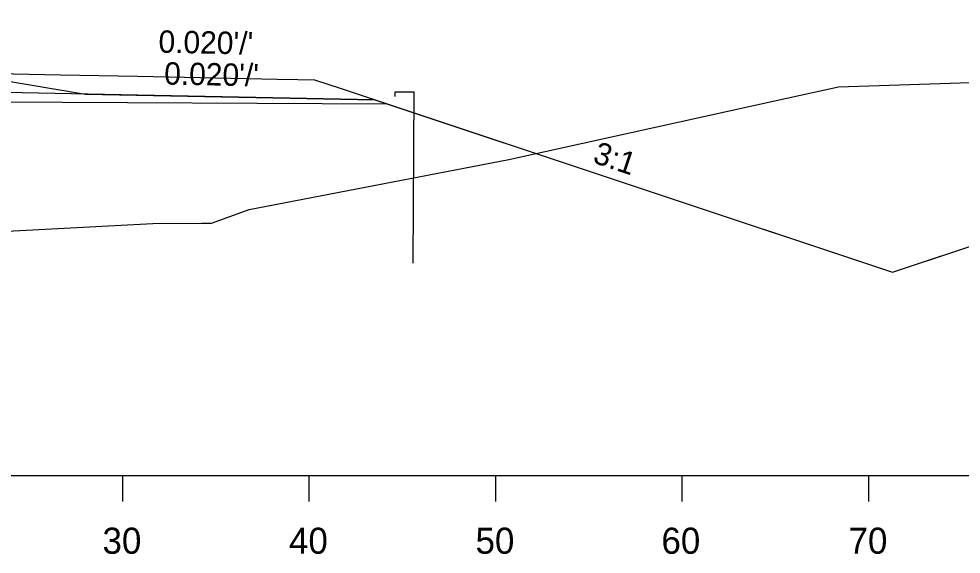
# Model space of a CAD drawing. Extents: x 2829243 to 2838161, y 467639 to 474695.
# Drawn here: x 2832294.1 to 2832546.7, y 469949.2 to 470092.8 of the extents above; entities that cross this region are included whole.
import ezdxf

# ---------------------------------------------------------------- set-up
doc = ezdxf.new("R2010")
doc.units = 0
for name, color, linetype in [('R_Alt Surface', 7, 'Continuous'), ('R_Axis', 7, 'Continuous'), ('R_Axis Annot', 7, 'Continuous'), ('R_Detour', 7, 'Continuous'), ('R_Exist Surface', 7, 'Continuous'), ('R_Fin Surface', 7, 'Continuous'), ('R_Water', 7, 'Continuous'), ('R_Xsect Slope', 7, 'Continuous')]:
    doc.layers.add(name, color=color, linetype=linetype)

msp = doc.modelspace()

# ---------------------------------------------------------------- linework, layer by layer
at = {"layer": 'R_Alt Surface'}
msp.add_lwpolyline([(2832268.39, 470073.52), (2832325.89, 470072.37), (2832389.35, 470071.1)], dxfattribs=at)
at = {"layer": 'R_Axis'}
for p, q in [((2831421.96, 469970.29), (2832921.96, 469970.29)), ((2832321.96, 469963.29), (2832321.96, 469970.29)), ((2832371.96, 469963.29), (2832371.96, 469970.29)), ((2832421.96, 469963.29), (2832421.96, 469970.29)), ((2832471.96, 469963.29), (2832471.96, 469970.29)), ((2832521.96, 469963.29), (2832521.96, 469970.29))]:
    msp.add_line(p, q, dxfattribs=at)
at = {"layer": 'R_Detour'}
msp.add_lwpolyline([(2832268.39, 470078.52), (2832279.4, 470078.3), (2832288.39, 470078.12), (2832305.24, 470077.79), (2832325.89, 470077.37), (2832342.73, 470077.04), (2832363.39, 470076.62), (2832368.9, 470076.51), (2832373.39, 470076.42), (2832380.55, 470074.04), (2832389.35, 470071.1), (2832466.05, 470045.54), (2832528.3, 470024.79), (2832581.64, 470042.56), (2832716.63, 470088.59), (2832723.46, 470090.52), (2832731.53, 470092.77)], dxfattribs=at)
at = {"layer": 'R_Exist Surface'}
msp.add_lwpolyline([(2831891.2, 470066.21), (2831923.92, 470058.94), (2832009.96, 470036.62), (2832045.14, 470033.88), (2832075.41, 470031.51), (2832093.85, 470029.19), (2832165.67, 470027.94), (2832167.32, 470027.92), (2832170.89, 470027.85), (2832240.25, 470032.54), (2832255.72, 470032.55), (2832282.38, 470035.38), (2832330.03, 470037.9), (2832343.03, 470037.95), (2832345.71, 470038), (2832355.82, 470041.63), (2832425.43, 470055.06), (2832491.03, 470069.51), (2832499.96, 470071.51), (2832513.84, 470074.54), (2832570.91, 470076.45)], dxfattribs=at)
at = {"layer": 'R_Fin Surface'}
for points in [[(2832389.58, 470071.03), (2832528.3, 470024.79), (2832554.97, 470033.67), (2832581.64, 470042.56), (2832649.13, 470065.57), (2832716.63, 470088.59), (2832723.46, 470090.52), (2832726.78, 470091.45), (2832730.1, 470092.37), (2832731.99, 470092.68)], [(2831789.07, 470067.46), (2831789.07, 470067.45), (2831906.59, 470028.29), (2832046.96, 470075.08), (2832062.75, 470077.71), (2832096.96, 470083.41), (2832116.96, 470084.21), (2832165.15, 470085.17), (2832171.96, 470085.31), (2832179.86, 470085.15), (2832226.96, 470084.21), (2832237.43, 470083.79), (2832246.96, 470083.41), (2832281.16, 470077.71), (2832311.96, 470072.58), (2832389.58, 470071.03)]]:
    msp.add_lwpolyline(points, dxfattribs=at)
at = {"layer": 'R_Water'}
msp.add_line((2832041.26, 470071.93), (2832392.81, 470069.95), dxfattribs=at)
msp.add_lwpolyline([(2832394.99, 470071.96), (2832394.99, 470073.21), (2832399.99, 470073.18), (2832399.74, 470027.28)], dxfattribs=at)

# ---------------------------------------------------------------- texts
at = {"layer": 'R_Axis Annot'}
for s, p in [('30', (2832316.53, 469949.29)), ('40', (2832366.53, 469949.29)), ('50', (2832416.53, 469949.29)), ('60', (2832466.37, 469949.29)), ('70', (2832516.53, 469949.29))]:
    msp.add_text(s, height=7, dxfattribs=at).set_placement(p)
at = {"layer": 'R_Xsect Slope'}
for s, rotation, p in [("0.020'/'", 358.8542, (2832331.5, 470083.7)), ("0.020'/'", 358.856, (2832333.03, 470075.16)), ('3:1', 341.565, (2832447.69, 470054.29))]:
    msp.add_text(s, height=6, rotation=rotation, dxfattribs=at).set_placement(p)

doc.saveas('drawing.dxf')
